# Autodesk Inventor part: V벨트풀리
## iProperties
Created: 2015-03
Part Number: V벨트풀리
Material: Steel
Document SubType Name: Modeling
Designer: KYOUNG IL JANG
Density: 1 g/cm^3
CustomPartVersion: 1
Author: KYOUNG IL JANG
